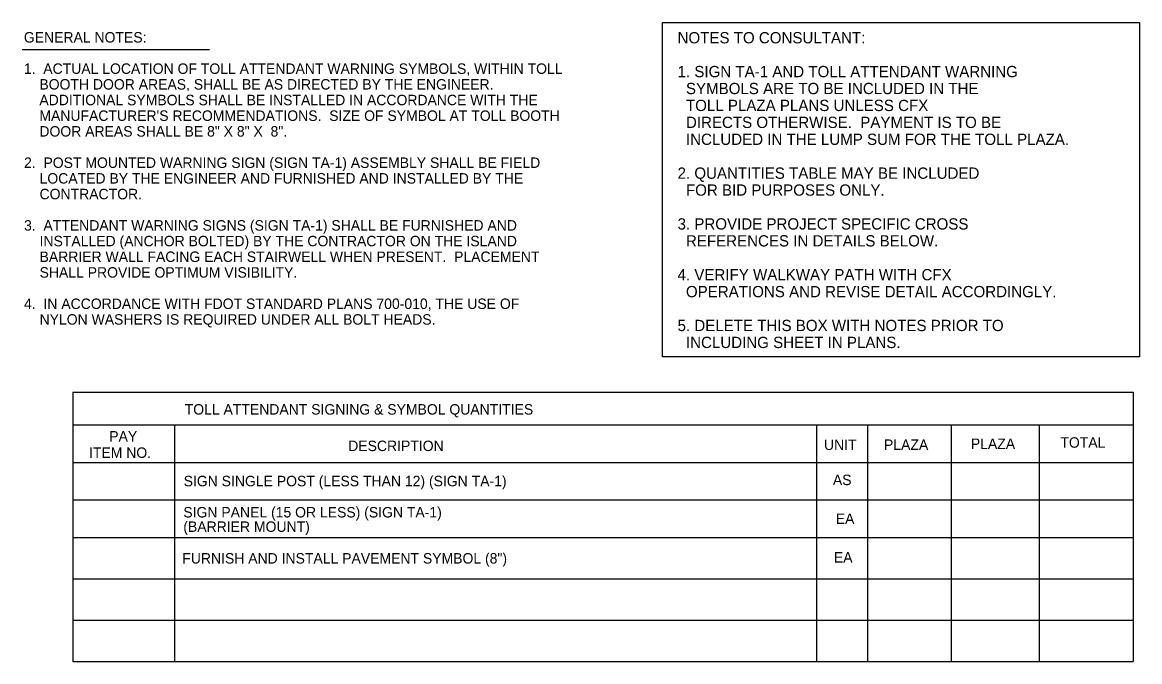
# Model space of a CAD drawing. Extents: x 53068 to 53703, y 9291 to 9710.
# Drawn here: x 53403.7 to 53703.1, y 9537.3 to 9708.6 of the extents above; entities that cross this region are included whole.
import ezdxf

# ---------------------------------------------------------------- set-up
doc = ezdxf.new("R2010")
doc.units = 0
for name, color, linetype in [('TextAlert', 7, 'Continuous'), ('TextNotes', 7, 'Continuous'), ('TextTables', 7, 'Continuous')]:
    doc.layers.add(name, color=color, linetype=linetype)

msp = doc.modelspace()

# ---------------------------------------------------------------- linework, layer by layer
at = {"layer": 'TextAlert'}
msp.add_lwpolyline([(53575.23, 9708.64), (53703.13, 9708.64), (53703.13, 9618.99), (53575.23, 9618.99)], close=True, dxfattribs=at)
at = {"layer": 'TextNotes'}
msp.add_line((53403.66, 9701.37), (53453.8, 9701.37), dxfattribs=at)
at = {"layer": 'TextTables'}
for p, q in [((53417.19, 9609.51), (53701.4, 9609.51)), ((53417.19, 9609.51), (53417.19, 9537.32)), ((53701.4, 9609.51), (53701.4, 9537.32)), ((53417.19, 9600.77), (53701.4, 9600.77)), ((53444.44, 9600.77), (53444.44, 9537.32)), ((53616.56, 9600.77), (53616.56, 9537.32)), ((53630.21, 9600.77), (53630.21, 9537.32)), ((53652.64, 9600.77), (53652.64, 9537.32)), ((53676.19, 9600.77), (53676.19, 9537.32)), ((53417.19, 9590.72), (53701.4, 9590.72)), ((53417.19, 9580.68), (53701.4, 9580.68)), ((53417.19, 9570.63), (53701.4, 9570.63)), ((53417.19, 9559.53), (53701.4, 9559.53)), ((53417.19, 9548.43), (53701.4, 9548.43)), ((53417.19, 9537.32), (53701.4, 9537.32))]:
    msp.add_line(p, q, dxfattribs=at)

# ---------------------------------------------------------------- texts
at = {"layer": 'TextAlert'}
for s, p in [('NOTES TO CONSULTANT:', (53579.28, 9703.01)), ('1. SIGN TA-1 AND TOLL ATTENDANT WARNING', (53579.28, 9693.94)), ('  SYMBOLS ARE TO BE INCLUDED IN THE', (53579.28, 9689.4)), ('  TOLL PLAZA PLANS UNLESS CFX', (53579.28, 9684.87)), ('  DIRECTS OTHERWISE.  PAYMENT IS TO BE', (53579.28, 9680.33)), ('  INCLUDED IN THE LUMP SUM FOR THE TOLL PLAZA.', (53579.28, 9675.79)), ('2. QUANTITIES TABLE MAY BE INCLUDED', (53579.28, 9666.72)), ('  FOR BID PURPOSES ONLY.', (53579.28, 9662.19)), ('3. PROVIDE PROJECT SPECIFIC CROSS', (53579.28, 9653.11)), ('  REFERENCES IN DETAILS BELOW.', (53579.28, 9648.58)), ('4. VERIFY WALKWAY PATH WITH CFX', (53579.28, 9639.51)), ('  OPERATIONS AND REVISE DETAIL ACCORDINGLY.', (53579.28, 9634.97)), ('5. DELETE THIS BOX WITH NOTES PRIOR TO', (53579.28, 9625.9)), ('  INCLUDING SHEET IN PLANS.', (53579.28, 9621.36))]:
    msp.add_text(s, height=3.024, dxfattribs=at).set_placement(p)
at = {"layer": 'TextNotes'}
for s, p in [('GENERAL NOTES:', (53404.07, 9703.23)), ('1.  ACTUAL LOCATION OF TOLL ATTENDANT WARNING SYMBOLS, WITHIN TOLL', (53404.07, 9694.83)), ('    BOOTH DOOR AREAS, SHALL BE AS DIRECTED BY THE ENGINEER.', (53404.07, 9690.63)), ('    ADDITIONAL SYMBOLS SHALL BE INSTALLED IN ACCORDANCE WITH THE', (53404.07, 9686.43)), ("    MANUFACTURER'S RECOMMENDATIONS.  SIZE OF SYMBOL AT TOLL BOOTH", (53404.07, 9682.23)), ('    DOOR AREAS SHALL BE 8" X 8" X  8".', (53404.07, 9678.03)), ('2.  POST MOUNTED WARNING SIGN (SIGN TA-1) ASSEMBLY SHALL BE FIELD ', (53404.12, 9669.63)), ('    LOCATED BY THE ENGINEER AND FURNISHED AND INSTALLED BY THE ', (53404.12, 9665.43)), ('    CONTRACTOR.', (53404.12, 9661.23)), ('3.  ATTENDANT WARNING SIGNS (SIGN TA-1) SHALL BE FURNISHED AND', (53404.12, 9652.83)), ('    INSTALLED (ANCHOR BOLTED) BY THE CONTRACTOR ON THE ISLAND', (53404.12, 9648.63)), ('    BARRIER WALL FACING EACH STAIRWELL WHEN PRESENT.  PLACEMENT', (53404.12, 9644.43)), ('    SHALL PROVIDE OPTIMUM VISIBILITY.   ', (53404.12, 9640.23)), ('4.  IN ACCORDANCE WITH FDOT STANDARD PLANS 700-010, THE USE OF', (53404.12, 9631.83)), ('    NYLON WASHERS IS REQUIRED UNDER ALL BOLT HEADS.', (53404.12, 9627.63))]:
    msp.add_text(s, height=2.8, dxfattribs=at).set_placement(p)
at = {"layer": 'TextTables'}
for s, p in [('TOLL ATTENDANT SIGNING & SYMBOL QUANTITIES', (53447.18, 9603.53)), ('PAY ', (53426.96, 9596.31)), ('DESCRIPTION', (53491.01, 9593.75)), ('UNIT', (53618.53, 9594.04)), ('PLAZA', (53634.61, 9594.06)), ('PLAZA', (53657.89, 9594.31)), ('TOTAL', (53681.88, 9594.65)), ('ITEM NO.', (53421.53, 9591.93)), ('SIGN SINGLE POST (LESS THAN 12) (SIGN TA-1)', (53446.9, 9584.32)), ('AS', (53620.92, 9584.63)), ('SIGN PANEL (15 OR LESS) (SIGN TA-1)', (53446.81, 9575.96)), ('EA', (53621.68, 9574.22)), ('(BARRIER MOUNT)', (53446.81, 9572.1)), ('FURNISH AND INSTALL PAVEMENT SYMBOL (8")', (53446.53, 9563.61)), ('EA', (53621.18, 9563.87))]:
    msp.add_text(s, height=2.8, dxfattribs=at).set_placement(p)

doc.saveas('drawing.dxf')
